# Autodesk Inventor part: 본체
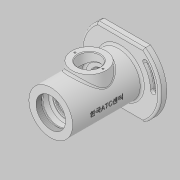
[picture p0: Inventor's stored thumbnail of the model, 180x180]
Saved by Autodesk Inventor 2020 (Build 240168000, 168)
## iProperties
Created: 2022-05
Part Number: 본체
Material: 일반
Document SubType Name: Modeling
Designer: User
Density: 1 g/cm^3
Appearance: 기본값
Author: User
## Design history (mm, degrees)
sketch "스케치1"
  geometry: L1 (0, 0)-(115, 0); L2 (115, 0)-(115, 32); L3 (115, 32)-(0, 32); L4 (0, 32)-(0, 0); L5 (0, 22.5)-(8, 22.5); L6 (8, 22.5)-(8, 24); L7 (8, 24)-(11, 24); L8 (11, 24)-(11, 22.5); L9 (11, 22.5)-(22, 22.5); L10 (22, 22.5)-(22, 17.5); L11 (22, 17.5)-(24.25, 17.5); L12 (24.25, 17.5)-(24.25, 18.5); L13 (24.25, 18.5)-(26, 18.5); L14 (26, 18.5)-(26, 17.5); L15 (26, 17.5)-(37, 17.5); L16 (37, 17.5)-(37, 27); L17 (37, 27)-(75, 27); L18 (75, 27)-(75, 17.5); L19 (75, 17.5)-(86, 17.5); L20 (86, 17.5)-(86, 15); L21 (86, 15)-(91, 15); L22 (91, 15)-(91, 11); L23 (91, 11)-(93.7, 11); L24 (93.7, 11)-(93.7, 15); L25 (93.7, 15)-(101, 15); L26 (115, 32)-(115, 36); L27 (115, 36)-(112, 36); L28 (112, 36)-(112, 32); L29 (101, 15)-(101, 20); L30 (101, 20)-(115, 30); L31 (8, 24)-(8, 32); L32 (8, 22.5)-(8, 0)
  constraints: 64 end point, 24 perpendicular, 8 point on line, 3 vertical, 2 horizontal
  dimensions: "d0" = 3 distance of L26.end L27.end; "d1" = 112 distance between parallel lines of L28 L4; "d2" = 64 diameter of L3 L1; "d3" = 45 diameter of L9 L1; "d4" = 54 diameter of L17 L1; "d5" = 22 diameter of L23 L1; "d6" = 30 diameter of L25 L1; "d7" = 40 diameter of L29.end L1; "d8" = 60 diameter of L30.end L1; "d9" = 72 diameter of L27 L1; "d10" = 35 diameter of L15 L1; "d11" = 35 diameter of L11 L1; "d12" = 48 diameter of L7 L1; "d13" = 37 diameter of L13 L1; "d14" = 14 horizontal distance of L30.end L29.end; "d15" = 7.3 distance of L24.end L25.end; "d16" = 5 distance of L20.end L21.end; "d17" = 29 horizontal distance of L30.end L20.end; "d18" = 11 distance of L18.end L19.end; "d19" = 11 distance of L14.end L15.end; "d20" = 38 distance of L16.end L17.end; "d21" = 1.75 distance of L12.end L13.end; "d22" = 4 horizontal distance of L13.end L10.end; "d23" = 8 distance of L5.start L5.end; "d24" = 3 distance of L6.end L7.end; "d25" = 30 diameter of L21 L1; "d26" = 35 diameter of L19 L1
revolve "회전1" stored, may be unused: angle "d27" = 90 deg
sketch "스케치2"
  geometry: C1 r 32 at (0, 0) reference; 2 further points
  constraints: 1 coincident
hole "구멍1" sketch "스케치2" at (0, 0) diameter "d28" = 43.376; stored, may be unused: countersink angle "d32" = 90 deg, drill point angle "d34" = 0 deg; dims "d29" = 8, "d30" = 4, "d31" = 2, "d33" = 9
node "작업 평면1"
sketch "스케치3"
  geometry: L1 (-47, -33.985)-(-47, 33.985); L2 (47, 33.985)-(47, -33.985); L3 (0, 0)-(0, 48); L4 (0, 0)-(-30.854, 36.77); L5 (0, 0)-(0, -48); L6 (0, 0)-(30.854, -36.77); A1 r 48 centre (0, 0) between (0, 48) and (-30.854, 36.77); A2 r 4 centre (-30.854, 36.77) between (-33.425, 39.834) and (-28.283, 33.706); A3 r 58 centre (0, 0) between (47, 33.985) and (-47, 33.985); A4 r 58 centre (0, 0) between (-47, -33.985) and (47, -33.985); A5 r 4 centre (0, 48) between (0, 52) and (0, 44); A6 r 4 centre (0, -48) between (0, -52) and (0, -44); A7 r 4 centre (30.854, -36.77) between (28.283, -33.706) and (33.425, -39.834); A8 r 52 centre (0, 0) between (0, -52) and (33.425, -39.834); A9 r 52 centre (0, 0) between (0, 52) and (-33.425, 39.834); A10 r 44 centre (0, 0) between (0, 44) and (-28.283, 33.706); A11 r 44 centre (0, 0) between (0, -44) and (28.283, -33.706); A12 r 48 centre (0, 0) between (0, -48) and (30.854, -36.77); A13 r 50.25 centre (0, 0) between (0, -50.25) and (32.3, -38.494); A14 r 45.75 centre (0, 0) between (0, -45.75) and (29.408, -35.047); A15 r 2.25 centre (0, -48) between (0, -45.75) and (0, -50.25); A16 r 2.25 centre (30.854, -36.77) between (32.3, -38.494) and (29.408, -35.047); A17 r 48 centre (0, 0) between (0, 48) and (-30.854, 36.77); A18 r 50.25 centre (0, 0) between (0, 50.25) and (-32.3, 38.494); A19 r 45.75 centre (0, 0) between (0, 45.75) and (-29.408, 35.047); A20 r 2.25 centre (0, 48) between (0, 45.75) and (0, 50.25); A21 r 2.25 centre (-30.854, 36.77) between (-32.3, 38.494) and (-29.408, 35.047); 3 further points
  constraints: 44 point on circle, 21 centre point, 12 end point, 12 tangent, 10 coincident, 3 vertical, 2 midpoint, 1 parallel, 1 vertical alignment
  dimensions: "d37" = 96 diameter of A1; "d38" = 40 deg angle of L3 L4; "d39" = 8 diameter of A2; "d40" = 58 radius of A3; "d41" = 58 radius of A4; "d42" = 94 distance between parallel lines of L2 L1; "d44" = 8 diameter of A5; "d47" = 40 deg angle of L6 L5; "d48" = 8 diameter of A6; "d49" = 8 diameter of A7; "d51" = 47 distance between parallel lines of L3 L1 (= 0.5 x d42); "d62" = 4.5 radial gap between concentric circles of A13 A14; "d65" = 4.5 radial gap between concentric circles of A19 A18
extrude "돌출1" join sketch "스케치3" distance "d52" = 10; taper "d53" = 0 deg
revolve "회전2" stored, may be unused: angle "d54" = 90 deg
extrude "돌출3" cut sketch "스케치3" distance "d58" = 4.4; taper "d59" = 0 deg
extrude "돌출4" cut sketch "스케치3" extent not by distance; stored distance "d60" = 0; taper "d61" = 0 deg
extrude "돌출5" cut sketch "스케치3" extent not by distance; stored distance "d63" = 0; taper "d64" = 0 deg
node "작업 평면2"
sketch "스케치4"
  geometry: C1 r 25 at (56, 0); 1 further point
  constraints: 1 centre point, 1 horizontal alignment
  dimensions: "d67" = 50 diameter of C1; "d68" = 56 distance of C1.centre point (0, 0)
extrude "돌출6" join sketch "스케치4" stored distance "d69" = 10; taper "d70" = 5 deg
sketch "스케치5"
  geometry: C1 r 25 at (0, 0) reference; 2 further points
  constraints: 1 coincident
hole "구멍2" sketch "스케치5" at (0, 0) diameter "d71" = 32; stored, may be unused: countersink angle "d75" = 90 deg, drill point angle "d77" = 0 deg; dims "d72" = 90, "d73" = 4, "d74" = 2, "d76" = 38
fillet "모깎기1" dims "d78" = 3
fillet "모깎기2" dims "d79" = 3
fillet "모깎기3" dims "d80" = 0.6
fillet "모깎기4" dims "d81" = 0.5
chamfer "모따기1" distance "d82" = 0.7; stored, may be unused: second distance "d83" = 2, angle "d84" = 30 deg
fillet "모깎기5" dims "d85" = 3
fillet "모깎기6" dims "d86" = 3
fillet "모깎기7" dims "d87" = 3
chamfer "모따기2" distance "d88" = 1; stored, may be unused: second distance "d89" = 2, angle "d90" = 30 deg
chamfer "모따기3" distance "d91" = 1; stored, may be unused: second distance "d92" = 2, angle "d93" = 30 deg
chamfer "모따기4" distance "d94" = 1; stored, may be unused: second distance "d95" = 2, angle "d96" = 30 deg
node "작업 평면3"
sketch "스케치6"
  geometry: L1 (56, -47)-(56, 47) reference; L2 (46, -44)-(46, 44) reference; 3 further points
  constraints: 1 horizontal alignment, 1 midpoint, 1 other
  dimensions: "d97" = 62 distance from line of point (-6, 0) L1
feature "엠보싱1" sketch "스케치6" dims "d0" = 3, "d1" = 112, "d2" = 64, "d3" = 45, "d4" = 54, "d5" = 22, "d6" = 30, "d7" = 40, "d8" = 60, "d9" = 72, "d10" = 35, "d11" = 35, "d12" = 48, "d13" = 37, "d14" = 14, "d15" = 7.3, "d16" = 5, "d17" = 29, "d18" = 11, "d19" = 11, "d20" = 38, "d21" = 1.75, "d22" = 4, "d23" = 8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
sketch "스케치7"
  geometry: L1 (0, 0)-(0, 20.5); C1 r 16 at (0, 0) reference; 2 further points
  constraints: 2 end point, 1 coincident, 1 vertical
  dimensions: "d100" = 20.5 distance of L1.start L1.end
hole "구멍3" sketch "스케치7" at (0, 20.5) diameter "d101" = 2.62111; stored, may be unused: countersink angle "d105" = 90 deg, drill point angle "d107" = 118 deg; dims "d102" = 6, "d103" = 4, "d104" = 2, "d106" = 8
fillet "모깎기8" dims "d111" = 3
chamfer "모따기5" distance "d112" = 1; stored, may be unused: second distance "d113" = 2, angle "d114" = 45 deg
node "솔리드1"
pattern_circular "원형 패턴1" dims angle "d109" = 360 deg
feature "A9D066F2-1C7D-4E18-AEED-F7BC21143FA4" dims "d71" = 32, "d72" = 90, "d73" = 4, "d74" = 2, "d75" = 90 deg, "d76" = 38, "d77" = 0
other parameters: "d57" = -13, "d66" = 38
